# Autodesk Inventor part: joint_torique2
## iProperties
Shininess: 64.0
Length Units: 11269
Angle Units: 11279
Time Units: 11290
Mass Units: 11283
Length Display Precision: 3
Angle Display Precision: 2
Compacted: True
Part Number: joint_torique2
Document SubType Name: Modeling
Created: 2004-05
Material: Par défaut
Designer: David
Density: 0.0
Volumn: 0.0
Area: 0.0
PropertySet Name: Model Information
Control State: 0
Master: False
Checked Out: False
Author: David
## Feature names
1. Révolution1 [Revolution]
